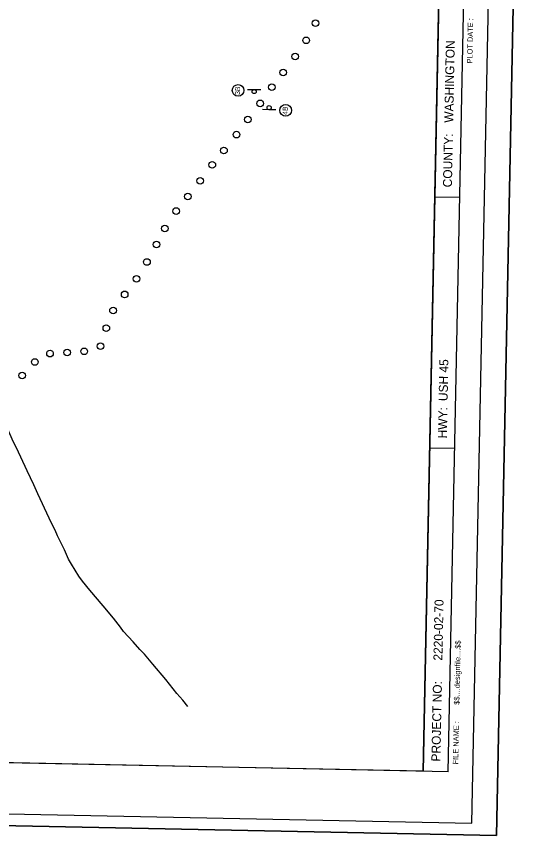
# Model space of a CAD drawing. Extents: x 345549 to 379569, y 127949 to 230467.
# Drawn here: x 364063 to 379569, y 178813 to 203528 of the extents above; entities that cross this region are included whole.
import ezdxf

# ---------------------------------------------------------------- set-up
doc = ezdxf.new("R2010")
doc.units = 0
for name, color, linetype in [('CA-TEXT', 7, 'Continuous'), ('CE-TOPO-CONC-SLAB', 7, 'Continuous'), ('Level 1', 7, 'Continuous'), ('P_MISC_NoPlot', 7, 'Continuous'), ('P_RDWY_Text', 7, 'Continuous'), ('PLT_Sheet_Border', 7, 'Continuous'), ('PLT_Sheet_Info', 7, 'Continuous'), ('SIGNS-POLES', 7, 'Continuous')]:
    doc.layers.add(name, color=color, linetype=linetype)

msp = doc.modelspace()

# ---------------------------------------------------------------- linework, layer by layer
at = {"layer": 'CA-TEXT'}
for centre in [(370748, 201295), (372182, 200693)]:
    msp.add_circle(centre, 176, dxfattribs=at)
at = {"layer": 'CE-TOPO-CONC-SLAB'}
for centre in [(373085, 203322), (372801, 202805), (372472, 202319), (372106, 201836), (371763, 201390), (371411, 200903), (371044, 200420), (370700, 199960), (370323, 199484), (369971, 199047), (369608, 198568), (369231, 198092), (368878, 197655), (368541, 197130), (368289, 196643), (368001, 196118), (367683, 195613), (367328, 195141), (366978, 194656), (366775, 194121), (366108, 193423), (366599, 193578), (365077, 193353), (365597, 193388), (364622, 193101), (364237, 192695)]:
    msp.add_circle(centre, 100, dxfattribs=at)
at = {"layer": 'Level 1'}
msp.add_line((368905, 183097), (368912, 183090), dxfattribs=at)
for points in [[(364585, 189398), (364389, 189819), (364064, 190509), (363978, 190679), (363530, 191670)], [(365630, 187156), (365512, 187434), (365438, 187591), (365303, 187854), (365229, 188024), (365162, 188162), (365051, 188394), (364714, 189122), (364585, 189398)], [(368912, 183090), (368905, 183097), (368565, 183518), (368176, 183984), (367922, 184287), (367786, 184432), (367588, 184659), (367296, 184967), (367198, 185106), (366994, 185376), (366678, 185748), (366276, 186220), (366053, 186491), (365948, 186642), (365726, 187000), (365630, 187156)], [(369231, 182706), (369079, 182895), (368905, 183097)]]:
    msp.add_lwpolyline(points, dxfattribs=at)
at = {"layer": 'P_MISC_NoPlot'}
msp.add_lwpolyline([(347087, 181344), (347770, 215283), (369369, 214831), (369345, 213590), (376990, 213459), (376331, 180755)], close=True, dxfattribs=at)
at = {"layer": 'P_RDWY_Text'}
msp.add_lwpolyline([(345549, 179477), (346576, 230467), (379569, 229803), (378542, 178813)], close=True, dxfattribs=at)
at = {"layer": 'PLT_Sheet_Border'}
for points in [[(378542, 178813), (379569, 229803), (346576, 230467), (345549, 179477)], [(377800, 179188), (378799, 228828), (347306, 229462), (346306, 179822)]]:
    msp.add_lwpolyline(points, close=True, dxfattribs=at)
at = {"layer": 'PLT_Sheet_Info'}
for p, q in [((376331, 180755), (377282, 227996)), ((377081, 180740), (378032, 227981)), ((377430, 198062), (376680, 198077)), ((377277, 190488), (376527, 190503)), ((377081, 180740), (347087, 181344)), ((378542, 178813), (378573, 180313)), ((378542, 178813), (377043, 178843))]:
    msp.add_line(p, q, dxfattribs=at)
at = {"layer": 'SIGNS-POLES'}
for p, q in [((371029, 201324), (371231, 201323)), ((371233, 201322), (371435, 201319)), ((371685, 200711), (371482, 200715)), ((371889, 200707), (371686, 200709))]:
    msp.add_line(p, q, dxfattribs=at)
for centre in [(371234, 201259), (371684, 200773)]:
    msp.add_circle(centre, 62.6, dxfattribs=at)

# ---------------------------------------------------------------- texts
at = {"layer": 'CA-TEXT'}
for s, p in [('3B', (370805, 201158)), ('4B', (372239, 200556))]:
    msp.add_text(s, height=150, rotation=88.8468, dxfattribs=at).set_placement(p)
at = {"layer": 'PLT_Sheet_Info'}
for s, height, p in [('PLOT DATE :', 162, (377811, 202105)), ('WASHINGTON            ', 270, (377235, 200316)), ('COUNTY:', 270, (377196, 198367)), ('USH 45         ', 270, (377066, 191918)), ('HWY:', 270, (377043, 190793)), ('2220-02-70', 270, (376908, 184089)), ('$$....designfile....$$', 162, (377422, 182759)), ('PROJECT NO:', 270, (376847, 181045)), ('FILE NAME :', 162, (377385, 180959))]:
    msp.add_text(s, height=height, rotation=88.8462, dxfattribs=at).set_placement(p)

doc.saveas('drawing.dxf')
